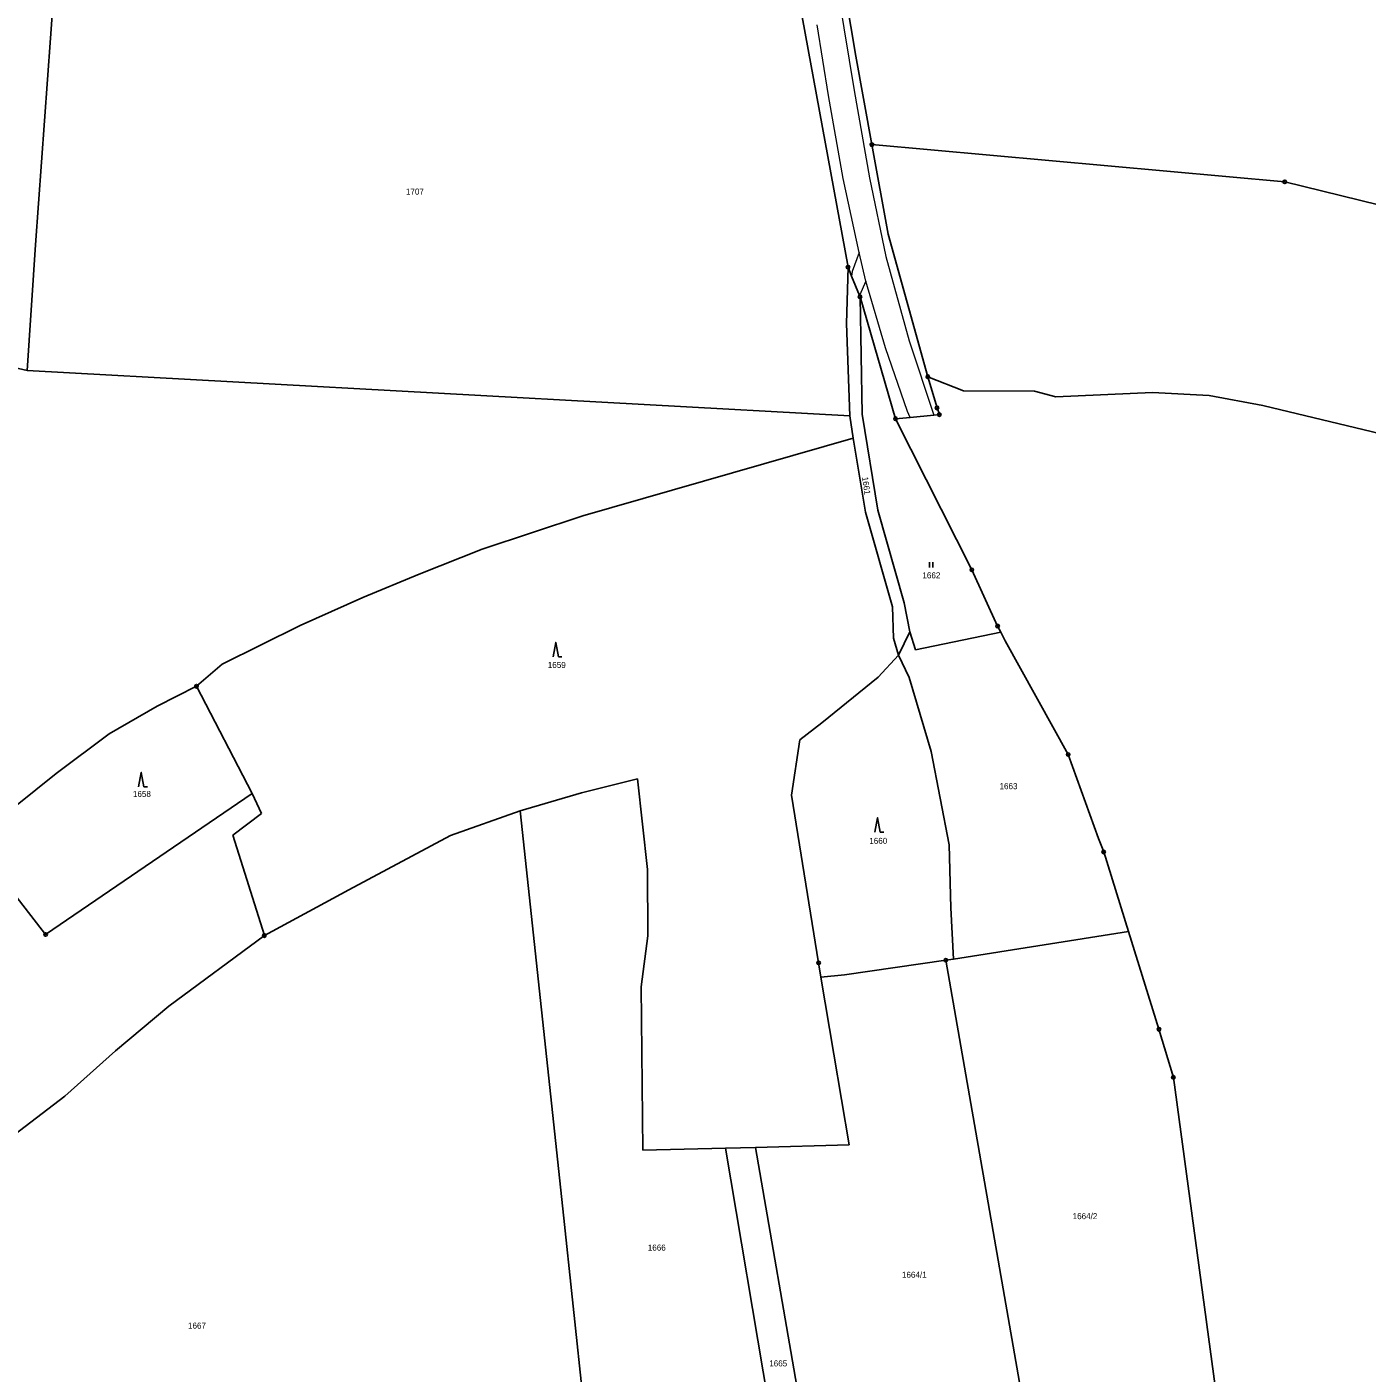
# Model space of a CAD drawing. Extents: x -601131 to -597152, y -1058536 to -1055911.
# Drawn here: x -598947 to -598569.8, y -1057934.2 to -1057555.3 of the extents above; entities that cross this region are included whole.
import ezdxf
from ezdxf.enums import TextEntityAlignment as Align

# ---------------------------------------------------------------- set-up
doc = ezdxf.new("R2010")
doc.units = 0
doc.header["$LTSCALE"] = 0.68
for name, color, linetype, lineweight in [('1', 7, 'Continuous', 25), ('3', 7, 'Continuous', 25), ('4', 7, 'Continuous', 13), ('8', 7, 'Continuous', 25)]:
    doc.layers.add(name, color=color, linetype=linetype, lineweight=lineweight)
doc.layers.add('2', color=7, linetype='Continuous')

msp = doc.modelspace()

# ---------------------------------------------------------------- linework, layer by layer
at = {"layer": '1'}
for p, q in [((-598722.72, -1057508.96), (-598713.68, -1057563.59)), ((-598939.22, -1057542.65), (-598944.53, -1057616.7)), ((-598715.87, -1057622.96), (-598728.78, -1057552.54)), ((-598713.68, -1057563.59), (-598709.15, -1057588.46)), ((-598709.15, -1057588.46), (-598592.97, -1057598.94)), ((-598709.15, -1057588.46), (-598704.55, -1057613.66)), ((-598592.97, -1057598.94), (-598493.59, -1057623.29)), ((-598704.55, -1057613.66), (-598693.41, -1057653.77)), ((-598944.53, -1057616.7), (-598946.92, -1057652)), ((-598715.87, -1057622.96), (-598716.27, -1057638.85)), ((-598714.85, -1057625.48), (-598715.87, -1057622.96)), ((-598712.63, -1057630.94), (-598714.85, -1057625.48)), ((-598712.49, -1057631.3), (-598712.63, -1057630.94)), ((-598712.49, -1057631.3), (-598711.85, -1057664.37)), ((-598702.52, -1057665.62), (-598712.49, -1057631.3)), ((-598716.27, -1057638.85), (-598715.32, -1057664.83)), ((-598946.92, -1057652), (-598980.09, -1057644.35)), ((-598831.12, -1057658.42), (-598946.92, -1057652)), ((-598690.82, -1057662.56), (-598693.41, -1057653.77)), ((-598693.41, -1057653.77), (-598683.41, -1057657.74)), ((-598683.41, -1057657.74), (-598663.41, -1057657.82)), ((-598663.41, -1057657.82), (-598657.35, -1057659.45)), ((-598657.35, -1057659.45), (-598630.16, -1057658.21)), ((-598630.16, -1057658.21), (-598614.23, -1057659.1)), ((-598715.32, -1057664.83), (-598831.12, -1057658.42)), ((-598614.23, -1057659.1), (-598599.17, -1057661.85)), ((-598599.17, -1057661.85), (-598549.7, -1057673.73)), ((-598715.32, -1057664.83), (-598714.41, -1057671.04)), ((-598711.85, -1057664.37), (-598707.48, -1057691.3)), ((-598698.4, -1057665.23), (-598702.52, -1057665.62)), ((-598681.04, -1057708.12), (-598702.52, -1057665.62)), ((-598691.72, -1057664.61), (-598698.4, -1057665.23)), ((-598690.16, -1057664.46), (-598691.72, -1057664.61)), ((-598690.82, -1057662.56), (-598690.16, -1057664.46)), ((-598790.47, -1057692.97), (-598714.41, -1057671.04)), ((-598714.41, -1057671.04), (-598710.93, -1057691.87)), ((-598710.93, -1057691.87), (-598703.36, -1057718.52)), ((-598707.48, -1057691.3), (-598700.03, -1057717.43)), ((-598818.87, -1057702.29), (-598790.47, -1057692.97)), ((-598836.6, -1057709.37), (-598818.87, -1057702.29)), ((-598852.4, -1057715.94), (-598836.6, -1057709.37)), ((-598673.78, -1057723.96), (-598681.04, -1057708.12)), ((-598870.1, -1057723.78), (-598852.4, -1057715.94)), ((-598703.36, -1057718.52), (-598703.1, -1057727.32)), ((-598700.03, -1057717.43), (-598698.5, -1057725.54)), ((-598892.04, -1057734.69), (-598870.1, -1057723.78)), ((-598701.66, -1057732.15), (-598698.5, -1057725.54)), ((-598698.5, -1057725.54), (-598696.84, -1057730.68)), ((-598696.84, -1057730.68), (-598672.88, -1057725.68)), ((-598672.88, -1057725.68), (-598673.78, -1057723.96)), ((-598672.88, -1057725.68), (-598671.61, -1057728.11)), ((-598703.1, -1057727.32), (-598701.66, -1057732.15)), ((-598671.61, -1057728.11), (-598653.93, -1057760.1)), ((-598701.66, -1057732.15), (-598707.39, -1057738.35)), ((-598698.62, -1057738.43), (-598701.66, -1057732.15)), ((-598899.25, -1057740.9), (-598892.04, -1057734.69)), ((-598899.25, -1057740.9), (-598910.36, -1057746.51)), ((-598883.59, -1057771.11), (-598899.25, -1057740.9)), ((-598707.39, -1057738.35), (-598723.29, -1057751.21)), ((-598692.43, -1057759.26), (-598698.62, -1057738.43)), ((-598910.36, -1057746.51), (-598923.86, -1057754.27)), ((-598723.29, -1057751.21), (-598729.46, -1057755.94)), ((-598923.86, -1057754.27), (-598938.76, -1057765.44)), ((-598729.46, -1057755.94), (-598731.77, -1057771.57)), ((-598687.43, -1057785.49), (-598692.43, -1057759.26)), ((-598653.93, -1057760.1), (-598645.34, -1057783.73)), ((-598938.76, -1057765.44), (-598962.31, -1057784.33)), ((-598775.11, -1057766.91), (-598790.89, -1057770.87)), ((-598772.33, -1057792.44), (-598775.11, -1057766.91)), ((-598941.71, -1057810.74), (-598883.59, -1057771.11)), ((-598883.59, -1057771.11), (-598880.91, -1057776.72)), ((-598790.89, -1057770.87), (-598808.19, -1057775.97)), ((-598731.77, -1057771.57), (-598724.16, -1057818.74)), ((-598880.91, -1057776.72), (-598889.06, -1057782.84)), ((-598808.19, -1057775.97), (-598827.77, -1057782.87)), ((-598796.16, -1057887.96), (-598808.19, -1057775.97)), ((-598889.06, -1057782.84), (-598880.14, -1057811.06)), ((-598827.77, -1057782.87), (-598856.33, -1057798.19)), ((-598962.31, -1057784.33), (-598941.71, -1057810.74)), ((-598686.94, -1057803.23), (-598687.43, -1057785.49)), ((-598645.34, -1057783.73), (-598643.91, -1057787.52)), ((-598643.91, -1057787.52), (-598636.94, -1057809.89)), ((-598772.18, -1057811.12), (-598772.33, -1057792.44)), ((-598856.33, -1057798.19), (-598880.14, -1057811.06)), ((-598686.23, -1057817.66), (-598686.94, -1057803.23)), ((-598880.14, -1057811.06), (-598906.99, -1057830.9)), ((-598774.14, -1057825.51), (-598772.18, -1057811.12)), ((-598724.16, -1057818.74), (-598723.49, -1057822.76)), ((-598688.35, -1057817.97), (-598716.85, -1057822.12)), ((-598686.23, -1057817.66), (-598688.35, -1057817.97)), ((-598688.35, -1057817.97), (-598660.6, -1057977.28)), ((-598723.49, -1057822.76), (-598716.85, -1057822.12)), ((-598719.87, -1057844.39), (-598723.49, -1057822.76)), ((-598773.6, -1057871.48), (-598774.14, -1057825.51)), ((-598906.99, -1057830.9), (-598922.07, -1057843.47)), ((-598628.37, -1057837.42), (-598624.3, -1057850.97)), ((-598922.07, -1057843.47), (-598936.34, -1057856.22)), ((-598715.56, -1057869.97), (-598719.87, -1057844.39)), ((-598624.3, -1057850.97), (-598611.39, -1057946.59)), ((-598936.34, -1057856.22), (-598965.34, -1057878.43)), ((-598741.96, -1057870.67), (-598715.56, -1057869.97)), ((-598750.38, -1057870.93), (-598773.6, -1057871.48)), ((-598750.38, -1057870.93), (-598741.96, -1057870.67)), ((-598730.29, -1057990.06), (-598750.38, -1057870.93)), ((-598721.44, -1057988.44), (-598741.96, -1057870.67)), ((-598784.14, -1057999.95), (-598796.16, -1057887.96))]:
    msp.add_line(p, q, dxfattribs=at)
msp.add_lwpolyline([(-598686.23, -1057817.66), (-598636.94, -1057809.89), (-598628.37, -1057837.42)], dxfattribs=at)
at = {"layer": '3'}
for p, q in [((-598692.971, -1057707.5), (-598692.971, -1057706)), ((-598691.97, -1057707.5), (-598691.97, -1057706)), ((-598797.38, -1057732.57), (-598796.384, -1057732.57)), ((-598914.05, -1057769.16), (-598913.054, -1057769.16)), ((-598706.82, -1057781.92), (-598705.824, -1057781.92))]:
    msp.add_line(p, q, dxfattribs=at)
for points in [[(-598797.38, -1057732.57), (-598798.13, -1057728.57), (-598798.88, -1057732.57)], [(-598914.05, -1057769.16), (-598914.8, -1057765.16), (-598915.55, -1057769.16)], [(-598706.82, -1057781.92), (-598707.57, -1057777.92), (-598708.32, -1057781.92)]]:
    msp.add_lwpolyline(points, dxfattribs=at)
at = {"layer": '4'}
for p, q in [((-598719.29, -1057541.7), (-598714.15, -1057573.28)), ((-598721.38, -1057574.61), (-598724.53, -1057554.73)), ((-598717.2, -1057597.97), (-598721.38, -1057574.61)), ((-598714.15, -1057573.28), (-598709.83, -1057597.82)), ((-598712.77, -1057618.86), (-598717.2, -1057597.97)), ((-598709.83, -1057597.82), (-598705.2, -1057619.94)), ((-598712.77, -1057618.86), (-598714.71, -1057624.16)), ((-598710.89, -1057626.93), (-598712.77, -1057618.86)), ((-598705.2, -1057619.94), (-598698.71, -1057643.67)), ((-598714.71, -1057624.16), (-598714.85, -1057625.48)), ((-598710.89, -1057626.93), (-598712.63, -1057630.94)), ((-598705.34, -1057645.62), (-598710.89, -1057626.93)), ((-598699.12, -1057663.54), (-598705.34, -1057645.62)), ((-598698.71, -1057643.67), (-598691.72, -1057664.61)), ((-598698.4, -1057665.23), (-598699.12, -1057663.54))]:
    msp.add_line(p, q, dxfattribs=at)
at = {"layer": '8'}
for centre, radius in [((-598709.15, -1057588.4599), 0.5), ((-598709.15, -1057588.4599), 0.0303), ((-598592.97, -1057598.9399), 0.5), ((-598592.97, -1057598.9399), 0.0303), ((-598715.87, -1057622.9599), 0.5), ((-598715.87, -1057622.9599), 0.0303), ((-598712.49, -1057631.2999), 0.5), ((-598712.49, -1057631.2999), 0.0303), ((-598693.41, -1057653.7699), 0.5), ((-598693.41, -1057653.7699), 0.0303), ((-598690.82, -1057662.5599), 0.5), ((-598702.52, -1057665.6199), 0.5), ((-598702.52, -1057665.6199), 0.0303), ((-598690.82, -1057662.5599), 0.0303), ((-598690.16, -1057664.4599), 0.5), ((-598690.16, -1057664.4599), 0.0303), ((-598681.04, -1057708.1199), 0.5), ((-598681.04, -1057708.1199), 0.0303), ((-598673.78, -1057723.9599), 0.5), ((-598673.78, -1057723.9599), 0.0303), ((-598899.25, -1057740.8999), 0.5), ((-598899.25, -1057740.8999), 0.0303), ((-598653.93, -1057760.0999), 0.5), ((-598653.93, -1057760.0999), 0.0303), ((-598643.91, -1057787.5199), 0.5), ((-598643.91, -1057787.5199), 0.0303), ((-598941.71, -1057810.7399), 0.5), ((-598941.71, -1057810.7399), 0.0303), ((-598880.14, -1057811.0599), 0.5), ((-598880.14, -1057811.0599), 0.0303), ((-598724.16, -1057818.7399), 0.5), ((-598724.16, -1057818.7399), 0.0303), ((-598688.35, -1057817.9699), 0.5), ((-598688.35, -1057817.9699), 0.0303), ((-598628.37, -1057837.4199), 0.5), ((-598628.37, -1057837.4199), 0.0303), ((-598624.3, -1057850.9699), 0.5), ((-598624.3, -1057850.9699), 0.0303)]:
    msp.add_circle(centre, radius, dxfattribs=at)

# ---------------------------------------------------------------- texts
at = {"layer": '2'}
for s, p in [('1707', (-598837.78, -1057602.532)), ('1662', (-598692.41, -1057710.532)), ('1659', (-598797.85, -1057735.752)), ('1663', (-598670.71, -1057769.862)), ('1658', (-598914.61, -1057772.052)), ('1660', (-598707.36, -1057785.252)), ('1664/2', (-598649.18, -1057890.865)), ('1666', (-598769.7, -1057899.712)), ('1664/1', (-598697.22, -1057907.365)), ('1667', (-598899.11, -1057921.672)), ('1665', (-598735.52, -1057932.302))]:
    msp.add_text(s, height=1.7, dxfattribs=at).set_placement(p, align=Align.CENTER)
msp.add_text('1661', height=1.7, rotation=278, dxfattribs=at).set_placement((-598711.5817, -1057684.5577), align=Align.CENTER)

doc.saveas('drawing.dxf')
